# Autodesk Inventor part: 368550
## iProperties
Created: 2006-08
Part Number: 368550
Material: A2
Description: Federring
Vendor: Autodesk Inc.
Document SubType Name: Modeling
Standard: DIN 127
Designer: I.Baliuc
Standards Organization: DIN
Language: de-DE
Size Designation: A 6
Categories: <MemberInstance Version="R10.0.0"><Categories><Category DisplayName="Schrauben" InternalName="e4da775c-781d-43d5-af7c-5136215cf5a6" Mnemonic="FSTN"><Category Di
Density: 8.08 g/cm^3
Mass: 0.962691 g
Surface Area: 2.48728 cm^2
Volume: 0.119145 cm^3
Abmessung: A 6
Author: T.Messerschmitt
Comments: DIN 127 - A 6
Revision Number: 368550
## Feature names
1. Körper [Extrusion]
2. Schnitt [Extrusion]
